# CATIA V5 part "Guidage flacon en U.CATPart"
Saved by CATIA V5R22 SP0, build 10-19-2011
Part number: Guidage flacon en U
Bounding box of the stored display mesh (mm): x -45.25 to 45.25, y 0 to 107.406, z 0 to 16.6
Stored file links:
  D:\PER\CAO_PER_MODIF_2025\CAO_PER_pick&place_2024P\Sous_Ensemble_Flacon\newnewu.CATPart
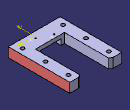
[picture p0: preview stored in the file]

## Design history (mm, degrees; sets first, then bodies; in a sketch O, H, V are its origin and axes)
Body1 (main body)
  Sketch1 on xy-plane, origin (0, 0, 0), H (1, 0, 0), V (0, 1, 0)
    point P1 (-45.25, 0)
    line L1 (-45.25, 0) -> (0, 0)
    point P2 (0, 0)
    point P3 (0, 27.406)
    line L2 (0, 27.406) -> (-25.25, 27.406)
    line L3 (-25.25, 27.406) -> (-25.25, 107.406)
    line L4 (-25.25, 107.406) -> (-45.25, 107.406)
    line L5 (-45.25, 107.406) -> (-45.25, 0)
    line L6 (0, 27.406) -> (0, 0)
    distance L2 L1 = 27.406
    distance L6 L3 = 25.25
    distance L5 L3 = 20
    distance L2 L4 = 80
    coincidence: P1 H, P2 V, P3 V, O P2
    horizontal: L1 H, L2 H, L4 H
    vertical: L3 V, L5 V, L6 V
  Pad1: profile Sketch1, direction (0, 0, 1), length 16.6
  Sketch2 on start face of Pad1, origin (0, 0, 0), H (1, 0, 0), V (0, -1, 0)
    circle A1 centre (-35.25, -15) radius 3.25
    point P1 (-35.25, -15)
    circle A2 centre (-35.25, -55) radius 3.25
    point P2 (-35.25, -55)
    circle A3 centre (-35.25, -95) radius 3.25
    point P3 (-35.25, -95)
    construction line L1 (-35.25, -55) -> (-35.25, -15)
    axis line L2 (-35.25, -95) -> (-35.25, -55)
    reference projected line E1 (-45.25, 0) -> (0, 0) from edge [start face of Pad1 | face of Pad1 from Sketch1.L1]
    reference projected line E2 (-45.25, -107.406) -> (-45.25, 0) from edge [start face of Pad1 | face of Pad1 from Sketch1.L5]
    radius A1 = 3.25
    radius A2 = 3.25
    radius A3 = 3.25
    distance P1 E1 = 15
    distance P1 E2 = 10
    distance P2 P3 = 40
    distance P1 P2 = 40
    vertical: L2 V, L1 V
  Pocket1: profile Sketch2, direction (0, 0, 1), through (limit type 3)
  Sketch3 on start face of Pad1, origin (0, 0, 0), H (1, 0, 0), V (0, -1, 0)
    point P1 (-35.25, -15)
    point P2 (-30.25, -12.1132)
    point P3 (-35.25, -9.2265)
    point P4 (-40.25, -12.1132)
    point P5 (-40.25, -17.8868)
    point P6 (-35.25, -20.7735)
    point P7 (-30.25, -17.8868)
    point P8 (-32.75, -10.6699)
    line L1 (-30.25, -12.1132) -> (-35.25, -9.2265)
    line L2 (-35.25, -9.2265) -> (-40.25, -12.1132)
    line L3 (-40.25, -12.1132) -> (-40.25, -17.8868)
    line L4 (-40.25, -17.8868) -> (-35.25, -20.7735)
    line L5 (-35.25, -20.7735) -> (-30.25, -17.8868)
    line L6 (-30.25, -17.8868) -> (-30.25, -12.1132)
    construction line L7 (-35.25, -15) -> (-32.75, -10.6699)
    construction circle A1 centre (-35.25, -15) radius 5.7735
    construction arc A2 centre (-35.25, -20.7735) radius 5.7735 from (-40.25, -17.8868) to (-30.25, -17.8868) cw
    construction arc A3 centre (-35.25, -9.2265) radius 5.7735 from (-40.25, -12.1132) to (-30.25, -12.1132) ccw
    point P9 (-35.25, -55)
    point P10 (-30.25, -52.1132)
    point P11 (-35.25, -49.2265)
    point P12 (-40.25, -52.1132)
    point P13 (-40.25, -57.8868)
    point P14 (-35.25, -60.7735)
    point P15 (-30.25, -57.8868)
    point P16 (-32.75, -50.6699)
    line L8 (-30.25, -52.1132) -> (-35.25, -49.2265)
    line L9 (-35.25, -49.2265) -> (-40.25, -52.1132)
    line L10 (-40.25, -52.1132) -> (-40.25, -57.8868)
    line L11 (-40.25, -57.8868) -> (-35.25, -60.7735)
    line L12 (-35.25, -60.7735) -> (-30.25, -57.8868)
    line L13 (-30.25, -57.8868) -> (-30.25, -52.1132)
    construction line L14 (-35.25, -55) -> (-32.75, -50.6699)
    construction circle A4 centre (-35.25, -55) radius 5.7735
    construction arc A5 centre (-35.25, -60.7735) radius 5.7735 from (-40.25, -57.8868) to (-30.25, -57.8868) cw
    construction arc A6 centre (-35.25, -49.2265) radius 5.7735 from (-40.25, -52.1132) to (-30.25, -52.1132) ccw
    point P17 (-35.25, -95)
    point P18 (-30.25, -92.1132)
    point P19 (-35.25, -89.2265)
    point P20 (-40.25, -92.1132)
    point P21 (-40.25, -97.8868)
    point P22 (-35.25, -100.7735)
    point P23 (-30.25, -97.8868)
    point P24 (-32.75, -90.6699)
    line L15 (-30.25, -92.1132) -> (-35.25, -89.2265)
    line L16 (-35.25, -89.2265) -> (-40.25, -92.1132)
    line L17 (-40.25, -92.1132) -> (-40.25, -97.8868)
    line L18 (-40.25, -97.8868) -> (-35.25, -100.7735)
    line L19 (-35.25, -100.7735) -> (-30.25, -97.8868)
    line L20 (-30.25, -97.8868) -> (-30.25, -92.1132)
    construction circle A7 centre (-35.25, -95) radius 5.7735
    construction arc A8 centre (-35.25, -100.7735) radius 5.7735 from (-40.25, -97.8868) to (-30.25, -97.8868) cw
    construction arc A9 centre (-35.25, -89.2265) radius 5.7735 from (-40.25, -92.1132) to (-30.25, -92.1132) ccw
    reference projected circle E1 centre (-35.25, -95) radius 3.25 from edge [start face of Pad1 | face of Pocket1 from Sketch2.A3]
    reference projected circle E2 centre (-35.25, -55) radius 3.25 from edge [start face of Pad1 | face of Pocket1 from Sketch2.A2]
    reference projected circle E3 centre (-35.25, -15) radius 3.25 from edge [start face of Pad1 | face of Pocket1 from Sketch2.A1]
    distance L17 L20 = 10
    coincidence: A1 P2, A1 P3, A1 P4, A1 P5, A1 P6, A1 P7, A2 P1, A3 P1, A4 P10, A4 P11, A4 P12, A4 P13, A4 P14, A4 P15, A5 P9, A6 P9, A7 P18, A7 P19, A7 P20, A7 P21, A7 P22, A7 P23, A8 P17, A9 P17, P7 L13, P15 L20
    midpoint: P8 L1, P16 L8, P24 L15
    parallelism: L1 L4, L8 L11, L15 L18, L6 L13, L13 L20
    concentricity: P17 E1, P9 E2, P1 E3
    vertical: L20 V
  Pocket2: profile Sketch3, direction (0, 0, 1), length 6
  Chamfer1: length 1, angle 45, on edge [start face of Pad1 | face of Pocket2 from Sketch3.L6]; edge [start face of Pad1 | face of Pocket2 from Sketch3.L1]; edge [start face of Pad1 | face of Pocket2 from Sketch3.L2]; edge [start face of Pad1 | face of Pocket2 from Sketch3.L3]; edge [start face of Pad1 | face of Pocket2 from Sketch3.L4]; edge [start face of Pad1 | face of Pocket2 from Sketch3.L5]; edge [start face of Pad1 | face of Pocket2 from Sketch3.L8]; edge [start face of Pad1 | face of Pocket2 from Sketch3.L13]; edge [start face of Pad1 | face of Pocket2 from Sketch3.L12]; edge [start face of Pad1 | face of Pocket2 from Sketch3.L11]; edge [start face of Pad1 | face of Pocket2 from Sketch3.L10]; edge [start face of Pad1 | face of Pocket2 from Sketch3.L9]; edge [start face of Pad1 | face of Pocket2 from Sketch3.L16]; edge [start face of Pad1 | face of Pocket2 from Sketch3.L15]; edge [start face of Pad1 | face of Pocket2 from Sketch3.L20]; edge [start face of Pad1 | face of Pocket2 from Sketch3.L19]; edge [start face of Pad1 | face of Pocket2 from Sketch3.L18]; edge [start face of Pad1 | face of Pocket2 from Sketch3.L17]
  Chamfer2: length 5, angle 30, on edge [face of Pad1 from Sketch1.L4 | face of Pad1 from Sketch1.L3]
  Mirror1: of the body so far, about face of Pad1 from Sketch1.L6
  Sketch4 on face of Pad1, origin (0, 0, 0), H (1, 0, 0), V (0, -1, 0)
    line L1 (-26.25, -20) -> (-19.25, -20)
    line L2 (23.75, 0) -> (-26.25, 0)
    line L3 (-26.25, 0) -> (-26.25, -20)
    reference projected line E1 (-29.25, -18.4641) -> (-29.25, -11.5359) from edge [start face of Pad1 | face of Chamfer1]
    line L4 (-19.25, -20) -> (-19.25, -30)
    line L5 (-19.25, -30) -> (23.75, -30)
    line L6 (23.75, -30) -> (23.75, 0)
    reference projected line E2 (0, 0) -> (-45.25, 0) from edge [face of Pad1 | face of Pad1]
    distance L3 E1 = 3
    distance L4 L3 = 7
    distance L2 L5 = 30
    distance L2 L1 = 20
    distance L6 L3 = 50
    horizontal: L1 H, L2 H, L5 H
    vertical: L3 V, L4 V, L6 V
    coincidence: L2 E2
  Pocket3: profile Sketch4, direction (0, 0, 1), length 10
  Sketch5 on end face of Pocket3, origin (0, 0, 10), H (1, 0, 0), V (0, -1, 0)
    point P1 (-13.45, -17.2)
    point P2 (8.95, -2.8)
    reference projected line E1 (23.75, -27.406) -> (23.75, 0) from edge [face of Pad1 | face of Pocket3 from Sketch4.L6]
    reference projected line E2 (-26.25, 0) -> (-26.25, -20) from edge [face of Pad1 | face of Pocket3 from Sketch4.L3]
    point P3 (8.95, -2.8)
    point P4 (-13.45, -17.2)
    reference projected line E3 (-26.25, -20) -> (-19.25, -20) from edge [face of Pad1 | face of Pocket3 from Sketch4.L1]
    reference projected line E4 (23.75, 0) -> (-26.25, 0) from edge [face of Pad1 | end face of Pocket3]
    distance P2 E1 = 14.8
    distance P1 E2 = 12.8
    distance P4 E3 = 2.8
    distance E4 P3 = 2.8
    coincidence: P3 P2, P4 P1
  DatumCurve1
  Sketch6 on end face of Pocket3, origin (-13.45, 2.8, 10), H (1, 0, 0), V (0, -1, 0)
    point P1 (0, -18.4308)
    reference projected arc E1 centre (0, -18.4308) radius 1.55 from (1.55, -18.4308) to (-1.55, -18.4308) ccw from edge of DatumCurve1
    concentricity: P1 E1
  Hole1: placed by Sketch6, at (-13.45, 21.2308, 10) direction (0, 0, 1), diameter 2.459, through (limit type 3), threaded "M3", thread diameter 3, thread depth 6.6, pitch 0.5
  DatumCurve2
  Sketch7 on end face of Pocket3, origin (8.95, 17.2, 10), H (1, 0, 0), V (0, -1, 0)
    point P1 (-0.2, 6.2692)
    reference projected arc E1 centre (-0.2, 6.2692) radius 1.55 from (-1.75, 6.2692) to (1.35, 6.2692) ccw from edge of DatumCurve2
    concentricity: P1 E1
  Hole2: placed by Sketch7, at (8.75, 10.9308, 10) direction (0, 0, 1), diameter 2.459, through (limit type 3), threaded "M3", thread diameter 3, thread depth 6.6, pitch 0.5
